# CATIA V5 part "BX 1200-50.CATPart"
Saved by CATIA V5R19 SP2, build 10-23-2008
Part number: BX 1200-50
Bounding box of the stored display mesh (mm): x -59.975 to 59.975, y -59.975 to 59.975, z 0 to 260
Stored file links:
  C:\Users\Bora\Desktop\3D Katı model\BX serisi\BX 1200\BX 1200-50.CATPart
  C:\Program Files\Dassault Systemes\B19\intel_a\reffiles\standard\MetricThickPitch.txt
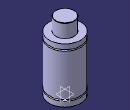
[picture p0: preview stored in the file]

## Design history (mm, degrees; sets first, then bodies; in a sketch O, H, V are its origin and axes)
Body1 (main body)
  Sketch1 on yz-plane, origin (0, 0, 0), H (0, 1, 0), V (0, 0, 1)
    point P1 (60, 185)
    point P2 (60, 190)
    arc A1 centre (60, 187.5) radius 2.5 from (60, 190) to (60, 185) ccw
    point P3 (60, 20)
    point P4 (60, 25)
    arc A2 centre (60, 22.5) radius 2.5 from (60, 25) to (60, 20) ccw
    point P5 (60, 190)
    line L1 (60, 209) -> (60, 190)
    point P8 (35, 259)
    line L2 (35, 259) -> (35, 209)
    point P10 (35, 259)
    arc A3 centre (34, 259) radius 1 from (35, 259) to (34, 260) ccw
    point P11 (60, 25)
    point P12 (60, 185)
    line L3 (60, 185) -> (60, 25)
    point P14 (60, 20)
    line L4 (60, 20) -> (60, 0)
    line L5 (34, 260) -> (0, 260)
    point P15 (0, 260)
    line L6 (35, 209) -> (60, 209)
    line L7 (60, 0) -> (0, 0)
    tangency: L5 A3
    coincidence: P15 V, P1 P12, P2 P5, P3 P14, P4 P11, P8 P10
    horizontal: L6 H, L7 H
  Shaft1: profile Sketch1, axis Sketch1.V, angle 360
  Sketch2 on face of Shaft1 from Sketch1.L7, origin (0, 0, 0), H (1, 0, 0), V (0, -1, 0)
    point P1 (32.5, 0)
    distance P1 V = 32.5
  Hole1: placed by Sketch2, at (32.5, 0, 0) direction (0, 0, 1), diameter 8.376, depth 10, threaded "M10", thread diameter 10, thread depth 10, pitch 1.5
  CircPattern1: of Hole1, instances 4, angular step 90, axis from xy-plane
